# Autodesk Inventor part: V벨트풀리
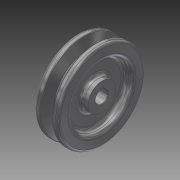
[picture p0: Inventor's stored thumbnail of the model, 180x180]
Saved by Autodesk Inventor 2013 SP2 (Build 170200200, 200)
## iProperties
Created: 2015-11
Part Number: V벨트풀리
Material: 강철, 탄소
Document SubType Name: Modeling
Designer: mduedu
Density: 1 g/cm^3
Author: mduedu
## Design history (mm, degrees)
sketch "스케치1"
  geometry: L1 (-9.5, 0)-(9.5, 0); L2 (0, 0)-(0, 34.7); L3 (-4.825, 34.7)-(-9.5, 34.7); L4 (-9.5, 34.7)-(-9.5, 0); L5 (0, 25.7)-(-2.074, 25.7); L6 (-2.074, 25.7)-(-4.825, 34.7); L7 (4.825, 34.7)-(9.5, 34.7); L8 (9.5, 34.7)-(9.5, 0); L9 (0, 25.7)-(2.074, 25.7); L10 (2.074, 25.7)-(4.825, 34.7); L11 (-9.5, 32)-(9.5, 32); 3 further points
  constraints: 22 end point, 7 point on line, 4 perpendicular, 3 symmetric about line, 1 coincident, 1 horizontal, 1 horizontal alignment, 1 midpoint, 1 vertical
  dimensions: "d0" = 19 distance of L1.start L1.end; "d2" = 69.4 diameter of L2.end L1 (derived); "d3" = 34 deg angle of L10 L6; "d4" = 6.3 distance between parallel lines of L11 L9; "d5" = 2.7 distance between parallel lines of L7 L11; "d6" = 8 distance of point (4, 32) point (-4, 32); "d7" = 64 diameter of L11 L1
revolve "회전1" sketch "스케치1" stored, may be unused: angle "d8" = 90 deg
sketch "스케치2"
  geometry: C1 r 24 at (0, 0); C2 r 11 at (0, 0); 1 further point
  constraints: 2 centre point, 2 coincident
  dimensions: "d9" = 48 diameter of C1; "d10" = 22 diameter of C2
extrude "돌출1" cut sketch "스케치2" distance "d11" = 6; taper "d12" = 0 deg
fillet "모깎기1" dims "d13" = 3
fillet "모깎기2" dims "d14" = 3
fillet "모깎기3" dims "d15" = 1, "d16" = 0.5, "d17" = 2
hole "구멍1" diameter "d20" = 10; stored, may be unused: countersink angle "d24" = 90 deg, drill point angle "d26" = 118 deg; dims "d18" = 10, "d19" = 10, "d21" = 6, "d22" = 4, "d23" = 2, "d25" = 8
sketch "스케치3"
  geometry: L1 (-1.5, 0)-(1.5, 0); L2 (1.5, 0)-(1.5, 6.4); L3 (1.5, 6.4)-(-1.5, 6.4); L4 (-1.5, 6.4)-(-1.5, 0); 2 further points
  constraints: 8 end point, 2 parallel, 1 coincident, 1 horizontal, 1 midpoint, 1 perpendicular
  dimensions: "d27" = 3 distance of L2.end L3.end; "d29" = 6.4 distance of L3.end L1.start
extrude "돌출2" cut sketch "스케치3" stored distance "d30" = 6; taper "d31" = 0 deg
chamfer "모따기1" distance "d32" = 0.5; stored, may be unused: second distance "d33" = 2, angle "d34" = 45 deg
node "솔리드1"
mirror "대칭1"
